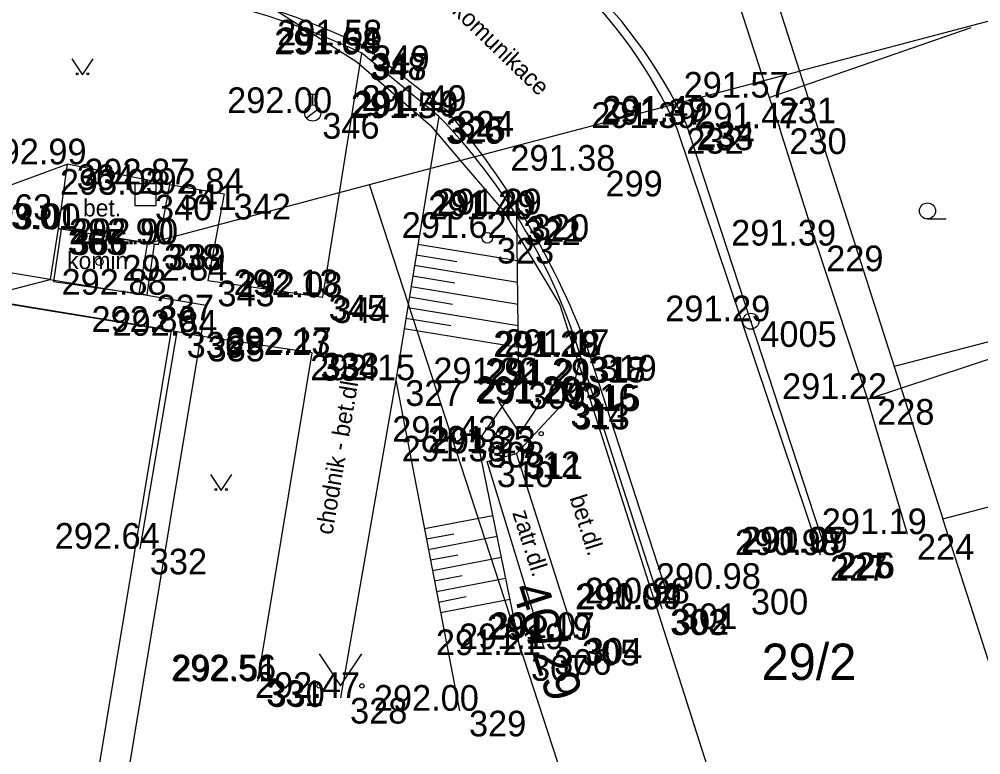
# Model space of a CAD drawing. Extents: x -599970 to -599524, y -1154772 to -1154457.
# Drawn here: x -599739.51 to -599717.03, y -1154688.06 to -1154670.86 of the extents above; entities that cross this region are included whole.
import ezdxf

# ---------------------------------------------------------------- set-up
doc = ezdxf.new("R2010")
doc.units = 0
for name, color, linetype in [('Z-BUDOVY', 7, 'Continuous'), ('Z-KATASTRALNI MAPA', 7, 'Continuous'), ('Z-PEVNE BODY-CISLO', 7, 'Continuous'), ('Z-PEVNE BODY-VYSKA', 7, 'Continuous'), ('Z-PEVNE BODY-ZNACKA', 7, 'Continuous'), ('Z-PLOT DRATENY', 7, 'Continuous'), ('Z-PLYNOVODNI SOUPATA HUP', 7, 'Continuous'), ('Z-PODROBNE BODY', 7, 'Continuous'), ('Z-PODROBNE BODY-CISLO', 7, 'Continuous'), ('Z-PODROBNE BODY-VYSKA', 7, 'Continuous'), ('Z-POPISY OBJEKTU A ZPEVNENYCH PLOCH', 7, 'Continuous'), ('Z-SCHODY', 7, 'Continuous'), ('Z-SRAFOVANI SVAHU', 7, 'Continuous'), ('Z-STOZARY SACHTY BEZ ROZLISENI', 7, 'Continuous'), ('Z-STROMY ZNACKY KULTUR', 7, 'Continuous'), ('Z-TERENNI HRANY PATY', 7, 'Continuous'), ('Z-VODOVODNI SACHTY SOUPATA HYDRANTY', 7, 'Continuous'), ('Z-VSTUPY VJEZDY', 7, 'Continuous'), ('Z-ZPEVNENE PLOCHY', 7, 'Continuous')]:
    doc.layers.add(name, color=color, linetype=linetype)

msp = doc.modelspace()

# ---------------------------------------------------------------- linework, layer by layer
at = {"layer": 'Z-BUDOVY'}
msp.add_lwpolyline([(-599736.68, -1154683.24), (-599735.82, -1154678.17), (-599746.96, -1154676.34)], dxfattribs=at)
at = {"layer": 'Z-KATASTRALNI MAPA'}
for p, q in [((-599725.18, -1154659.85), (-599721.27, -1154672.07)), ((-599683.62, -1154662.13), (-599721.27, -1154672.07)), ((-599681.43, -1154669.17), (-599719.06, -1154678.98)), ((-599729.2, -1154674.16), (-599721.27, -1154672.07)), ((-599721.27, -1154672.07), (-599719.06, -1154678.98)), ((-599729.9, -1154673.34), (-599729.2, -1154674.16)), ((-599731.32, -1154674.72), (-599729.2, -1154674.16)), ((-599729.2, -1154674.16), (-599728.2, -1154675.33)), ((-599736.51, -1154676.1), (-599731.32, -1154674.72)), ((-599724.53, -1154695.57), (-599731.32, -1154674.72)), ((-599728.2, -1154675.33), (-599726.87, -1154677.54)), ((-599736.71, -1154677.29), (-599736.51, -1154676.1)), ((-599738.79, -1154676.94), (-599736.71, -1154677.29)), ((-599740.48, -1154677.38), (-599735.95, -1154678.13)), ((-599739.18, -1154697.59), (-599735.95, -1154678.13)), ((-599719.06, -1154678.98), (-599717.92, -1154682.54)), ((-599717.92, -1154682.54), (-599708.78, -1154680.13)), ((-599716.78, -1154686.08), (-599717.92, -1154682.54))]:
    msp.add_line(p, q, dxfattribs=at)
for points in [[(-599834.98, -1154699.48), (-599751.66, -1154673.18), (-599740.79, -1154669.9), (-599738.46, -1154669.48), (-599735.86, -1154669.61), (-599733.7, -1154670.53), (-599731.62, -1154671.85), (-599729.9, -1154673.34)], [(-599738.79, -1154676.94), (-599747.8, -1154675.45), (-599748.46, -1154679.46)], [(-599736.51, -1154676.1), (-599738.6, -1154675.75), (-599738.79, -1154676.94)], [(-599748.46, -1154679.46), (-599747.72, -1154679.26), (-599740.48, -1154677.38), (-599738.79, -1154676.94)], [(-599738.49, -1154697.7), (-599735.14, -1154677.55), (-599736.71, -1154677.29)], [(-599726.87, -1154677.54), (-599722.78, -1154690.35), (-599724.39, -1154690.82), (-599723.03, -1154695.18)], [(-599728.31, -1154679.799), (-599727.81, -1154680.55), (-599727.31, -1154679.799)], [(-599732.5, -1154685.7), (-599732, -1154686.45), (-599731.5, -1154685.7)]]:
    msp.add_lwpolyline(points, dxfattribs=at)
for centre, radius in [((-599737.633, -1154676.53), 0.0875), ((-599728.31, -1154680.55), 0.05), ((-599727.31, -1154680.55), 0.05), ((-599732.5, -1154686.45), 0.05), ((-599731.5, -1154686.45), 0.05)]:
    msp.add_circle(centre, radius, dxfattribs=at)
at = {"layer": 'Z-PEVNE BODY-ZNACKA'}
for radius in [0.188, 0.188, 0.00896, 0.00896]:
    msp.add_circle((-599722.41, -1154677.92), radius, dxfattribs=at)
at = {"layer": 'Z-PLOT DRATENY'}
for p, q in [((-599721.98, -1154672.69), (-599717.26, -1154671.05)), ((-599719.68, -1154679.74), (-599714.93, -1154678.17))]:
    msp.add_line(p, q, dxfattribs=at)
for points in [[(-599722.84, -1154667.58), (-599723.56, -1154667.79), (-599721.98, -1154672.69), (-599721.73, -1154673.41)], [(-599720.87, -1154676.15), (-599719.68, -1154679.74)]]:
    msp.add_lwpolyline(points, dxfattribs=at)
at = {"layer": 'Z-PLYNOVODNI SOUPATA HUP'}
msp.add_circle((-599728.57, -1154675.97), 0.125, dxfattribs=at)
at = {"layer": 'Z-PODROBNE BODY'}
for p, q in [((-599731.48, -1154671.47), (-599731.48, -1154671.47)), ((-599731.55, -1154671.68), (-599731.55, -1154671.68)), ((-599731.5, -1154671.65), (-599731.5, -1154671.65)), ((-599721.98, -1154672.69), (-599721.98, -1154672.69)), ((-599732.65, -1154673.05), (-599732.65, -1154673.05)), ((-599729.7, -1154673.13), (-599729.7, -1154673.13)), ((-599729.51, -1154673), (-599729.51, -1154673)), ((-599729.76, -1154673.17), (-599729.76, -1154673.17)), ((-599723.91, -1154673.32), (-599723.91, -1154673.32)), ((-599723.88, -1154673.25), (-599723.88, -1154673.25)), ((-599724.14, -1154673.4), (-599724.14, -1154673.4)), ((-599721.73, -1154673.41), (-599721.73, -1154673.41)), ((-599738.39, -1154674.25), (-599738.39, -1154674.25)), ((-599726.03, -1154674.4), (-599726.03, -1154674.4)), ((-599735.99, -1154674.72), (-599735.99, -1154674.72)), ((-599734.72, -1154674.94), (-599734.72, -1154674.94)), ((-599736.56, -1154674.96), (-599736.56, -1154674.96)), ((-599727.95, -1154675.54), (-599727.95, -1154675.54)), ((-599727.88, -1154675.46), (-599727.88, -1154675.46)), ((-599727.75, -1154675.42), (-599727.75, -1154675.42)), ((-599738.6, -1154675.76), (-599738.6, -1154675.76)), ((-599738.53, -1154675.77), (-599738.53, -1154675.77)), ((-599728.57, -1154675.97), (-599728.57, -1154675.97)), ((-599736.35, -1154676.12), (-599736.35, -1154676.12)), ((-599736.25, -1154676.12), (-599736.25, -1154676.12)), ((-599720.87, -1154676.15), (-599720.87, -1154676.15)), ((-599735.1, -1154676.97), (-599735.1, -1154676.97)), ((-599736.52, -1154677.3), (-599736.52, -1154677.3)), ((-599732.5, -1154677.31), (-599732.5, -1154677.31)), ((-599732.41, -1154677.36), (-599732.41, -1154677.36)), ((-599735.82, -1154678.17), (-599735.82, -1154678.17)), ((-599735.33, -1154678.26), (-599735.33, -1154678.26)), ((-599732.69, -1154678.71), (-599732.69, -1154678.71)), ((-599732.66, -1154678.66), (-599732.66, -1154678.66)), ((-599726.43, -1154678.75), (-599726.43, -1154678.75)), ((-599726.38, -1154678.76), (-599726.38, -1154678.76)), ((-599726.17, -1154678.71), (-599726.17, -1154678.71)), ((-599730.71, -1154679.3), (-599730.71, -1154679.3)), ((-599727.83, -1154679.37), (-599727.83, -1154679.37)), ((-599726.62, -1154679.39), (-599726.62, -1154679.39)), ((-599726.55, -1154679.42), (-599726.55, -1154679.42)), ((-599726.85, -1154679.81), (-599726.85, -1154679.81)), ((-599726.8, -1154679.85), (-599726.8, -1154679.85)), ((-599719.68, -1154679.74), (-599719.68, -1154679.74)), ((-599728.79, -1154680.74), (-599728.79, -1154680.74)), ((-599727.96, -1154680.97), (-599727.96, -1154680.97)), ((-599728.57, -1154681.2), (-599728.57, -1154681.2)), ((-599727.89, -1154681.01), (-599727.89, -1154681.01)), ((-599718.75, -1154682.9), (-599718.75, -1154682.9)), ((-599736.68, -1154683.24), (-599736.68, -1154683.24)), ((-599720.78, -1154683.39), (-599720.78, -1154683.39)), ((-599720.64, -1154683.33), (-599720.64, -1154683.33)), ((-599720.6, -1154683.33), (-599720.6, -1154683.33)), ((-599722.63, -1154684.18), (-599722.63, -1154684.18)), ((-599724.29, -1154684.52), (-599724.29, -1154684.52)), ((-599724.52, -1154684.66), (-599724.52, -1154684.66)), ((-599724.48, -1154684.65), (-599724.48, -1154684.65)), ((-599726.58, -1154685.37), (-599726.58, -1154685.37)), ((-599726.51, -1154685.33), (-599726.51, -1154685.33)), ((-599727.23, -1154685.59), (-599727.23, -1154685.59)), ((-599727.77, -1154685.73), (-599727.77, -1154685.73)), ((-599733.96, -1154686.32), (-599733.96, -1154686.32)), ((-599733.93, -1154686.34), (-599733.93, -1154686.34)), ((-599732, -1154686.73), (-599732, -1154686.73)), ((-599729.22, -1154687.03), (-599729.22, -1154687.03))]:
    msp.add_line(p, q, dxfattribs=at)
at = {"layer": 'Z-SCHODY'}
msp.add_lwpolyline([(-599736.52, -1154677.3), (-599736.35, -1154676.12), (-599738.53, -1154675.77), (-599738.71, -1154676.99), (-599736.52, -1154677.3)], dxfattribs=at)
at = {"layer": 'Z-SRAFOVANI SVAHU'}
for points in [[(-599730.19, -1154676.12), (-599727.87, -1154676.5)], [(-599730.23, -1154676.37), (-599729.28, -1154676.52)], [(-599730.27, -1154676.61), (-599727.86, -1154677.01)], [(-599730.31, -1154676.86), (-599729.33, -1154677.02)], [(-599730.35, -1154677.11), (-599727.85, -1154677.52)], [(-599730.39, -1154677.35), (-599729.38, -1154677.52)], [(-599730.43, -1154677.6), (-599727.85, -1154678.02)], [(-599730.47, -1154677.85), (-599729.42, -1154678.02)], [(-599730.51, -1154678.09), (-599727.84, -1154678.53)], [(-599730.04, -1154682.77), (-599728.44, -1154682.46)], [(-599729.99, -1154683.01), (-599729.35, -1154682.89)], [(-599729.95, -1154683.26), (-599728.34, -1154682.95)], [(-599729.9, -1154683.5), (-599729.26, -1154683.38)], [(-599729.85, -1154683.75), (-599728.24, -1154683.44)], [(-599729.81, -1154683.99), (-599729.16, -1154683.87)], [(-599729.76, -1154684.24), (-599728.14, -1154683.93)], [(-599729.71, -1154684.49), (-599729.06, -1154684.36)], [(-599729.66, -1154684.73), (-599728.04, -1154684.42)]]:
    msp.add_lwpolyline(points, dxfattribs=at)
at = {"layer": 'Z-STOZARY SACHTY BEZ ROZLISENI'}
for p, q in [((-599736.31, -1154674.71), (-599736.81, -1154674.71)), ((-599736.81, -1154674.71), (-599736.81, -1154675.21)), ((-599736.31, -1154675.21), (-599736.31, -1154674.71)), ((-599736.81, -1154675.21), (-599736.31, -1154675.21))]:
    msp.add_line(p, q, dxfattribs=at)
at = {"layer": 'Z-STROMY ZNACKY KULTUR'}
msp.add_line((-599718.28, -1154675.528), (-599717.842, -1154675.528), dxfattribs=at)
for points in [[(-599738.28, -1154671.785), (-599738.03, -1154672.16), (-599737.78, -1154671.785)], [(-599735.04, -1154681.505), (-599734.79, -1154681.88), (-599734.54, -1154681.505)]]:
    msp.add_lwpolyline(points, dxfattribs=at)
for centre, radius in [((-599738.155, -1154672.135), 0.025), ((-599737.905, -1154672.135), 0.025), ((-599718.28, -1154675.34), 0.188), ((-599734.915, -1154681.855), 0.025), ((-599734.665, -1154681.855), 0.025)]:
    msp.add_circle(centre, radius, dxfattribs=at)
at = {"layer": 'Z-TERENNI HRANY PATY'}
for points in [[(-599727.77, -1154685.73), (-599728.79, -1154680.74), (-599727.83, -1154679.37), (-599727.88, -1154675.46)], [(-599730.71, -1154679.3), (-599729.22, -1154687.03)]]:
    msp.add_lwpolyline(points, dxfattribs=at)
at = {"layer": 'Z-VODOVODNI SACHTY SOUPATA HYDRANTY'}
for p, q in [((-599732.775, -1154672.612), (-599732.525, -1154672.612)), ((-599732.65, -1154672.862), (-599732.65, -1154672.612)), ((-599732.797, -1154673.166), (-599732.502, -1154672.934))]:
    msp.add_line(p, q, dxfattribs=at)
msp.add_circle((-599732.65, -1154673.05), 0.188, dxfattribs=at)
at = {"layer": 'Z-VSTUPY VJEZDY'}
for points in [[(-599720.87, -1154676.15), (-599721.73, -1154673.41)], [(-599718.75, -1154682.9), (-599719.68, -1154679.74)]]:
    msp.add_lwpolyline(points, dxfattribs=at)
at = {"layer": 'Z-ZPEVNENE PLOCHY'}
for points in [[(-599744.9, -1154671.03), (-599743.54, -1154674.4), (-599740.3, -1154674.95), (-599738.39, -1154674.25)], [(-599729.51, -1154673), (-599731.48, -1154671.47)], [(-599735.99, -1154674.72), (-599734.72, -1154674.94), (-599735.1, -1154676.97), (-599732.41, -1154677.36), (-599731.5, -1154671.65)], [(-599729.7, -1154673.13), (-599731.5, -1154671.65)], [(-599729.7, -1154673.13), (-599730.71, -1154679.3), (-599732, -1154686.73)], [(-599720.64, -1154683.33), (-599723.91, -1154673.32)], [(-599720.78, -1154683.39), (-599724.14, -1154673.4)], [(-599736.35, -1154676.12), (-599736.25, -1154676.12), (-599735.99, -1154674.72), (-599738.39, -1154674.25), (-599738.6, -1154675.76), (-599738.53, -1154675.77)], [(-599733.93, -1154686.34), (-599732.66, -1154678.66), (-599735.33, -1154678.26), (-599735.82, -1154678.17)], [(-599726.51, -1154685.33), (-599727.89, -1154681.01), (-599726.8, -1154679.85), (-599726.55, -1154679.42), (-599726.38, -1154678.76)], [(-599724.48, -1154684.65), (-599726.38, -1154678.76)], [(-599724.29, -1154684.52), (-599726.17, -1154678.71)], [(-599727.23, -1154685.59), (-599728.57, -1154681.2), (-599727.89, -1154681.01)]]:
    msp.add_lwpolyline(points, dxfattribs=at)
for centre, radius, start, end in [((-599734.212, -1154678.135), 11.372, 25.0528, 70.8958), ((-599734.095, -1154677.842), 10.901, 24.0446, 70.9101), ((-599739.28, -1154687.811), 18.107, 64.483, 98.8632), ((-599739.271, -1154688.14), 18.229, 64.7672, 98.4821), ((-599739.72, -1154682.833), 13.948, 16.9778, 44.0778), ((-599743.434, -1154684.976), 18.366, 19.95, 40.7001)]:
    msp.add_arc(centre, radius, start, end, dxfattribs=at)

# ---------------------------------------------------------------- texts
at = {"layer": 'Z-KATASTRALNI MAPA'}
msp.add_text('46/29', height=0.85, rotation=288, dxfattribs=at).set_placement((-599728.012, -1154684.172))
msp.add_text('29/2', height=0.85, dxfattribs=at).set_placement((-599722.156, -1154686.31))
at = {"layer": 'Z-PEVNE BODY-CISLO'}
msp.add_text(' 4005', height=0.6, dxfattribs=at).set_placement((-599722.41, -1154678.52))
at = {"layer": 'Z-PEVNE BODY-VYSKA'}
msp.add_text('291.29 ', height=0.6, dxfattribs=at).set_placement((-599724.41, -1154677.92))
at = {"layer": 'Z-PODROBNE BODY-CISLO'}
for s, p in [(' 349', (-599731.48, -1154672.07)), (' 348', (-599731.55, -1154672.28)), (' 347', (-599731.5, -1154672.25)), (' 231', (-599721.98, -1154673.29)), (' 346', (-599732.65, -1154673.65)), (' 325', (-599729.7, -1154673.73)), (' 324', (-599729.51, -1154673.6)), (' 326', (-599729.76, -1154673.77)), (' 233', (-599723.91, -1154673.92)), (' 234', (-599723.88, -1154673.85)), (' 232', (-599724.14, -1154674)), (' 230', (-599721.73, -1154674.01)), (' 364', (-599738.39, -1154674.85)), (' 299', (-599726.03, -1154675)), (' 341', (-599735.99, -1154675.32)), (' 363', (-599740.3, -1154675.55)), (' 342', (-599734.72, -1154675.54)), (' 340', (-599736.56, -1154675.56)), (' 322', (-599727.95, -1154676.14)), (' 321', (-599727.88, -1154676.06)), (' 320', (-599727.75, -1154676.02)), (' 365', (-599738.6, -1154676.36)), (' 366', (-599738.53, -1154676.37)), (' 323', (-599728.57, -1154676.57)), (' 338', (-599736.35, -1154676.72)), (' 339', (-599736.25, -1154676.72)), (' 229', (-599720.87, -1154676.75)), (' 343', (-599735.1, -1154677.57)), (' 337', (-599736.52, -1154677.9)), (' 345', (-599732.5, -1154677.91)), (' 344', (-599732.41, -1154677.96)), (' 336', (-599735.82, -1154678.77)), (' 335', (-599735.33, -1154678.86)), (' 334', (-599732.69, -1154679.31)), (' 333', (-599732.66, -1154679.26)), (' 318', (-599726.43, -1154679.35)), (' 317', (-599726.38, -1154679.36)), (' 319', (-599726.17, -1154679.31)), (' 327', (-599730.71, -1154679.9)), (' 309', (-599727.83, -1154679.97)), (' 316', (-599726.62, -1154679.99)), (' 315', (-599726.55, -1154680.02)), (' 314', (-599726.85, -1154680.41)), (' 313', (-599726.8, -1154680.45)), (' 228', (-599719.68, -1154680.34)), (' 308', (-599728.79, -1154681.34)), (' 312', (-599727.96, -1154681.57)), (' 311', (-599727.89, -1154681.61)), (' 310', (-599728.57, -1154681.8)), (' 224', (-599718.75, -1154683.5)), (' 332', (-599736.68, -1154683.84)), (' 227', (-599720.78, -1154683.99)), (' 225', (-599720.64, -1154683.93)), (' 226', (-599720.6, -1154683.93)), (' 300', (-599722.63, -1154684.78)), (' 301', (-599724.29, -1154685.12)), (' 303', (-599724.52, -1154685.26)), (' 302', (-599724.48, -1154685.25)), (' 305', (-599726.58, -1154685.97)), (' 304', (-599726.51, -1154685.93)), (' 307', (-599727.77, -1154686.33)), (' 306', (-599727.23, -1154686.19)), (' 331', (-599733.96, -1154686.92)), (' 330', (-599733.93, -1154686.94)), (' 328', (-599732, -1154687.33)), (' 329', (-599729.22, -1154687.63))]:
    msp.add_text(s, height=0.6, dxfattribs=at).set_placement(p)
at = {"layer": 'Z-PODROBNE BODY-VYSKA'}
for s, p in [('291.58 ', (-599733.48, -1154671.47)), ('291.64 ', (-599733.55, -1154671.68)), ('291.58 ', (-599733.5, -1154671.65)), ('291.57 ', (-599723.98, -1154672.69)), ('292.00 ', (-599734.65, -1154673.05)), ('291.49 ', (-599731.51, -1154673)), ('291.54 ', (-599731.76, -1154673.17)), ('291.49 ', (-599731.7, -1154673.13)), ('291.49 ', (-599725.88, -1154673.25)), ('291.39 ', (-599726.14, -1154673.4)), ('291.37 ', (-599725.91, -1154673.32)), ('291.47 ', (-599723.73, -1154673.41)), ('292.99 ', (-599740.39, -1154674.25)), ('291.38 ', (-599728.03, -1154674.4)), ('292.87 ', (-599737.99, -1154674.72)), ('293.03 ', (-599738.56, -1154674.96)), ('292.84 ', (-599736.72, -1154674.94)), ('291.40 ', (-599729.95, -1154675.54)), ('291.29 ', (-599729.88, -1154675.46)), ('291.29 ', (-599729.75, -1154675.42)), ('293.01 ', (-599740.6, -1154675.76)), ('293.00 ', (-599740.53, -1154675.77)), ('291.62 ', (-599730.57, -1154675.97)), ('292.90 ', (-599738.35, -1154676.12)), ('292.90 ', (-599738.25, -1154676.12)), ('291.39 ', (-599722.87, -1154676.15)), ('292.84 ', (-599737.1, -1154676.97)), ('292.88 ', (-599738.52, -1154677.3)), ('292.13 ', (-599734.5, -1154677.31)), ('292.08 ', (-599734.41, -1154677.36)), ('292.86 ', (-599737.82, -1154678.17)), ('292.84 ', (-599737.33, -1154678.26)), ('292.17 ', (-599734.66, -1154678.66)), ('292.23 ', (-599734.69, -1154678.71)), ('291.29 ', (-599728.43, -1154678.75)), ('291.18 ', (-599728.38, -1154678.76)), ('291.17 ', (-599728.17, -1154678.71)), ('292.15 ', (-599732.71, -1154679.3)), ('291.32 ', (-599729.83, -1154679.37)), ('291.29 ', (-599728.62, -1154679.39)), ('291.21 ', (-599728.55, -1154679.42)), ('291.29 ', (-599728.85, -1154679.81)), ('291.22 ', (-599721.68, -1154679.74)), ('291.20 ', (-599728.8, -1154679.85)), ('291.43 ', (-599730.79, -1154680.74)), ('291.35 ', (-599729.96, -1154680.97)), ('291.23 ', (-599729.89, -1154681.01)), ('291.38 ', (-599730.57, -1154681.2)), ('291.19 ', (-599720.75, -1154682.9)), ('292.64 ', (-599738.68, -1154683.24)), ('290.98 ', (-599722.78, -1154683.39)), ('290.97 ', (-599722.64, -1154683.33)), ('291.09 ', (-599722.6, -1154683.33)), ('290.98 ', (-599724.63, -1154684.18)), ('290.98 ', (-599726.29, -1154684.52)), ('291.04 ', (-599726.52, -1154684.66)), ('290.99 ', (-599726.48, -1154684.65)), ('291.19 ', (-599728.58, -1154685.37)), ('291.07 ', (-599728.51, -1154685.33)), ('291.19 ', (-599729.23, -1154685.59)), ('291.21 ', (-599729.77, -1154685.73)), ('292.56 ', (-599735.96, -1154686.32)), ('292.51 ', (-599735.93, -1154686.34)), ('292.47 ', (-599734, -1154686.73)), ('292.00 ', (-599731.22, -1154687.03))]:
    msp.add_text(s, height=0.6, dxfattribs=at).set_placement(p)
at = {"layer": 'Z-POPISY OBJEKTU A ZPEVNENYCH PLOCH'}
for s, rotation, p in [('asf. komunikace', 316.0414, (-599730.14, -1154669.99)), ('chodnik - bet.dl.', 80.4069, (-599732.19, -1154682.93)), ('bet.dl.', 287.7158, (-599726.65, -1154682.05)), ('zatr.dl.', 287.7158, (-599727.99, -1154682.4))]:
    msp.add_text(s, height=0.4, rotation=rotation, dxfattribs=at).set_placement(p)
for s, p in [('bet.', (-599738.02, -1154675.47)), ('komin', (-599738.39, -1154676.7))]:
    msp.add_text(s, height=0.4, dxfattribs=at).set_placement(p)

doc.saveas('drawing.dxf')
